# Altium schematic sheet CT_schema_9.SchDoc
size 274 x 160 mm
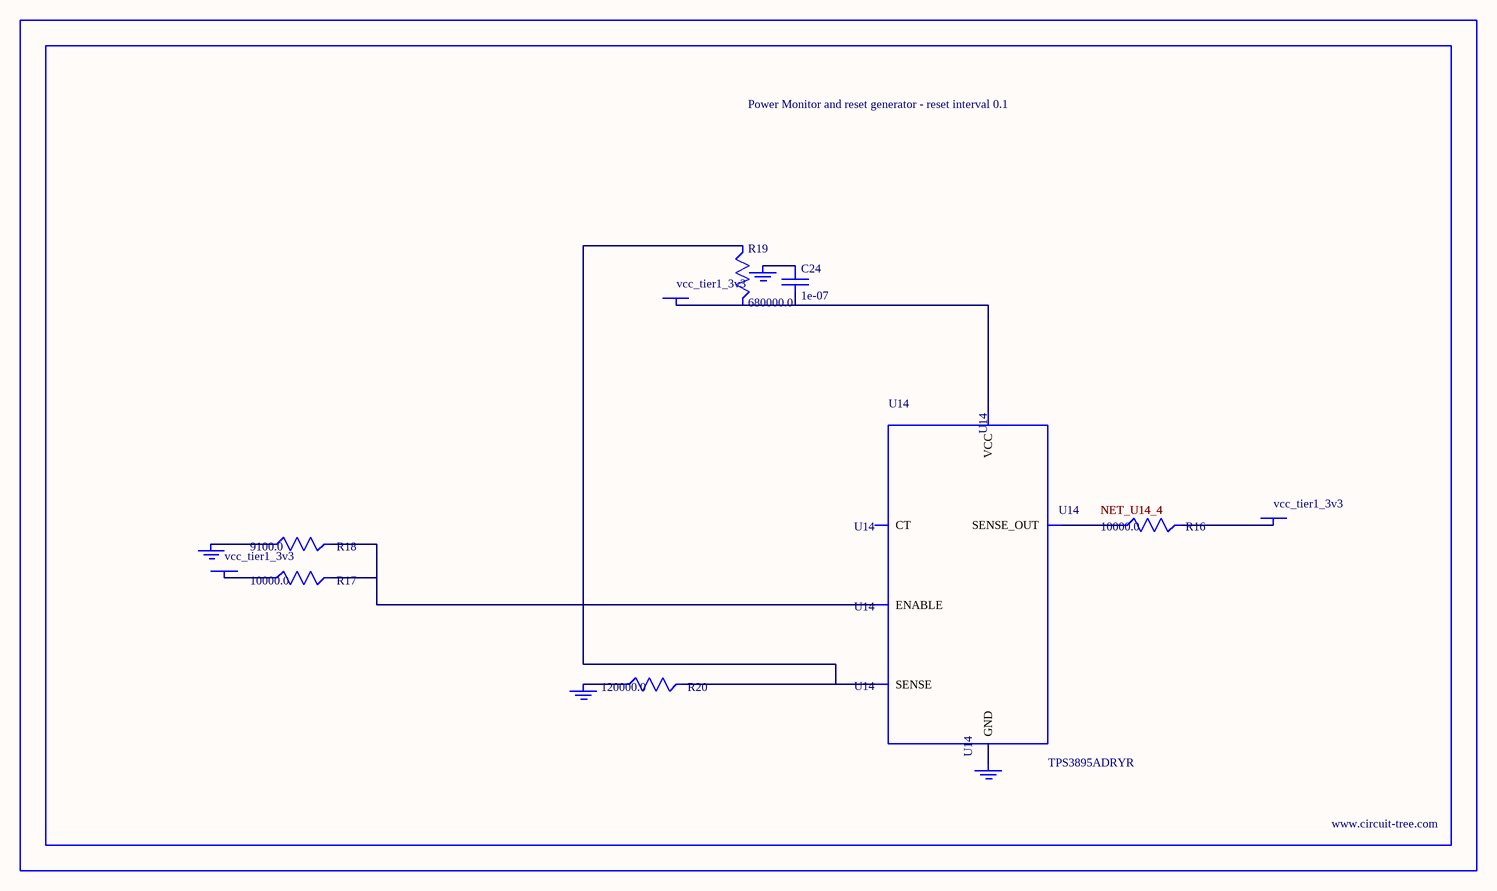
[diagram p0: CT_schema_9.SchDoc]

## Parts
BORDER8  (no value)
C24  1e-07  [C0402]
GND_INSTANCE_8_0  (no value)
GND_INSTANCE_8_1  (no value)
GND_INSTANCE_8_2  (no value)
GND_INSTANCE_8_3  (no value)
POWER_INSTANCE_8_0  vcc_tier1_3v3
POWER_INSTANCE_8_1  vcc_tier1_3v3
POWER_INSTANCE_8_2  vcc_tier1_3v3
R16  10000.0  [R0603]
R17  10000.0  [R0603]
R18  9100.0  [R0603]
R19  680000.0  [R0603]
R20  120000.0  [R0603]
U14  TPS3895ADRYR  [SON-6]

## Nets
NetC24_1: C24.1 GND_INSTANCE_8_2.0(GND)
NetC24_2: C24.2 POWER_INSTANCE_8_2.0(PWR) R19.2 U14.6(VCC)
NetGND_INSTANCE_8_0_0: GND_INSTANCE_8_0.0(GND) R18.1
NetGND_INSTANCE_8_1_0: GND_INSTANCE_8_1.0(GND) R20.1
NetGND_INSTANCE_8_3_0: GND_INSTANCE_8_3.0(GND) U14.2(GND)
NetPOWER_INSTANCE_8_0_0: POWER_INSTANCE_8_0.0(PWR) R17.1
NetPOWER_INSTANCE_8_1_0: POWER_INSTANCE_8_1.0(PWR) R16.2
NetR16_1: R16.1 U14.4(SENSE_OUT)
NetR17_2: R17.2 R18.2 U14.1(ENABLE)
NetR19_1: R19.1 R20.2 U14.3(SENSE)

Not connected (* = marked no-connect by the designer): U14 5(CT)

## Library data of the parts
BORDER8 = BORDER_PAGE8
C24 = C0402C104K3RACTU
GND_INSTANCE_8_0-GND_INSTANCE_8_3 = GND
POWER_INSTANCE_8_0-POWER_INSTANCE_8_2 = PWR
R16 R17 = RC0603JR-0710KL
R18 = RC0603JR-079K1L
R19 = RC0603JR-07680KL
R20 = RC0603JR-07120KL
